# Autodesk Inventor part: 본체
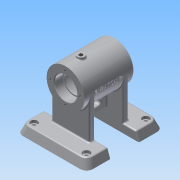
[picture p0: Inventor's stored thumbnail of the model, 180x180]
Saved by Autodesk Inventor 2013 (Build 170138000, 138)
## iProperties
Created: 2016-07
Part Number: 본체
Material: 알루미늄 6061
Document SubType Name: Modeling
Designer: Administrator
Density: 2.71 g/cm^3
Mass: 499.244 g
Surface Area: 539.605 cm^2
Volume: 184.223 cm^3
Author: Administrator
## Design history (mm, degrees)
sketch "스케치1"
  geometry: C1 r 27 at (0, 0); 1 further point
  constraints: 1 centre point, 1 coincident
  dimensions: "d0" = 54 diameter of C1
extrude "돌출1" new body sketch "스케치1" stored distance "d3" = 70; taper "d4" = 0 deg
node "작업 평면1"
sketch "스케치2"
  geometry: L1 (50, -55)-(-50, -55); L2 (-50, -55)-(-50, -20); L3 (-50, -20)-(50, -20); L4 (50, -20)-(50, -55); L5 (50, 20)-(-50, 20); L6 (-50, 20)-(-50, 55); L7 (-50, 55)-(50, 55); L8 (50, 55)-(50, 20); 1 further point
  constraints: 16 end point, 4 parallel, 2 collinear, 2 horizontal, 2 perpendicular
  dimensions: "d8" = 35 distance of L5.end L6.end; "d9" = 35 distance of L1.end L2.end; "d10" = 110 distance between parallel lines of L7 L1; "d11" = 50 distance from line of point (0, 0) L4; "d12" = 100 distance of L1.start L1.end; "d13" = 55 distance from line of point (0, 0) L1
extrude "돌출2" join sketch "스케치2" distance "d14" = 12; taper "d15" = 0 deg
sketch "스케치6"
  geometry: L1 (-48, 20.072)-(-48, -20.313); L2 (-48, -20.313)-(2, -20.313); L3 (2, -20.313)-(2, 20.072); L4 (2, 20.072)-(-48, 20.072); L5 (-27, -35)-(-27, 35) reference; 1 further point
  constraints: 8 end point, 2 parallel, 1 perpendicular, 1 vertical
  dimensions: "d28" = 21 distance between parallel lines of L1 L5; "d29" = 50 distance between parallel lines of L1 L3
extrude "돌출6" join sketch "스케치6" stored distance "d30" = 8; taper "d31" = 0 deg
sketch "스케치14"
  geometry: L1 (23, 70)-(23, 11.296); L2 (77, 70)-(77, 11.296); L3 (23, 11.296)-(77, 11.296); A1 r 27 centre (50, 70) between (77, 70) and (23, 70) reference; 1 further point
  constraints: 6 end point, 2 point on circle, 2 tangent, 1 parallel, 1 perpendicular, 1 vertical
extrude "돌출9" join sketch "스케치14" distance "d165" = 8; taper "d166" = 0 deg
sketch "스케치15"
  geometry: L1 (23, 70)-(23, 12); L2 (23, 12)-(77, 12); L3 (77, 12)-(77, 70); L4 (100, 12)-(0, 12) reference; A1 r 27 centre (50, 70) between (77, 70) and (23, 70) reference; 1 further point
  constraints: 6 end point, 2 point on circle, 2 tangent, 1 collinear, 1 parallel, 1 perpendicular, 1 vertical
extrude "돌출10" join sketch "스케치15" distance "d167" = 8; taper "d168" = 0 deg
feature "면 기울기1" dims angle "d169" = 20 deg
feature "면 기울기2" dims angle "d170" = 20 deg
feature "면 기울기3" dims angle "d171" = 20 deg
feature "면 기울기4" dims angle "d172" = 20 deg
feature "면 기울기5" dims angle "d173" = 20 deg
feature "면 기울기6" dims angle "d174" = 20 deg
fillet "모깎기17" dims "d175" = 10
fillet "모깎기18" dims "d176" = 2
fillet "모깎기19" dims "d177" = 2
fillet "모깎기20" dims "d178" = 2
fillet "모깎기21" dims "d179" = 2
fillet "모깎기22" dims "d180" = 2
fillet "모깎기23" dims "d181" = 2
fillet "모깎기24" dims "d182" = 2
fillet "모깎기25" dims "d183" = 2
fillet "모깎기26" dims "d184" = 2
sketch "스케치8"
  geometry: L1 (0, 35)-(0, -35); L2 (0, 35)-(16, 35); L3 (16, 35)-(16, 23); L4 (16, 23)-(14, 23); L5 (14, 23)-(14, 21); L6 (14, 21)-(22, 21); L7 (22, 21)-(22, -21); L8 (22, -21)-(14, -21); L9 (14, -21)-(14, -23); L10 (14, -23)-(16, -23); L11 (16, -23)-(16, -35); L12 (16, -35)-(0, -35); 2 further points
  constraints: 24 end point, 6 parallel, 5 perpendicular, 1 coincident, 1 midpoint, 1 vertical
  dimensions: "d46" = 70 distance of L1.start L1.end; "d48" = 32 diameter of L3 L1; "d49" = 28 diameter of L5 L1; "d50" = 44 diameter of L7 L1; "d51" = 28 diameter of L9 L1; "d52" = 32 diameter of L11 L1; "d53" = 12 distance of L2.end L3.end; "d54" = 42 distance of L6.end L7.end; "d55" = 12 distance of L10.end L11.end; "d56" = 2 distance of L4.end L5.end
revolve "회전1" sketch "스케치8" stored, may be unused: angle "d57" = 90 deg
fillet "모깎기9" dims "d58" = 0.3
fillet "모깎기10" dims "d59" = 3
chamfer "모따기1" distance "d60" = 1; stored, may be unused: second distance "d61" = 2, angle "d62" = 45 deg
sketch "스케치9"
  geometry: 2 further points
  constraints: 1 vertical alignment
  dimensions: "d63" = 21 distance of point (0, 0) point (0, 21)
hole "구멍1" sketch "스케치9" at (0, 21) diameter "d64" = 3.242; stored, may be unused: countersink angle "d68" = 90 deg, drill point angle "d70" = 118 deg; dims "d65" = 8, "d66" = 4, "d67" = 2, "d69" = 10
node "작업 평면2"
sketch "스케치10"
  geometry: L1 (27, 35)-(-27, 35) reference; C1 r 5 at (0, 13); 2 further points
  constraints: 1 centre point, 1 midpoint, 1 vertical alignment
  dimensions: "d76" = 22 distance from line of L1 C1.centre; "d77" = 10 diameter of C1
extrude "돌출8" join sketch "스케치10" stored distance "d78" = 8; taper "d79" = 0 deg
fillet "모깎기12" dims "d80" = 2
fillet "모깎기14" dims "d82" = 2
hole "구멍2" diameter "d85" = 5.188; stored, may be unused: countersink angle "d89" = 90 deg, drill point angle "d91" = 0 deg; dims "d83" = 10, "d84" = 10, "d86" = 19, "d87" = 4, "d88" = 2, "d90" = 20
sketch "스케치13"
  geometry: L1 (0, 0)-(-11.658, -18.657); L2 (0, 0)-(0, -35.07); L3 (-11.658, -18.657)-(-15.898, -25.441); L4 (-20.986, -22.262)-(-17.515, -16.707); L5 (-20.986, -22.262)-(-15.898, -25.441); L6 (-17.515, -16.707)-(-12.427, -19.887); 1 further point
  constraints: 12 end point, 2 perpendicular, 1 collinear, 1 point on line, 1 vertical, 2 other
  dimensions: "d113" = 32 deg angle of L1 L2; "d114" = 30 distance of L1.start L3.end; "d116" = 12 diameter of L4 L3; "d128" = 6.54998 distance between parallel lines of L5 L6
revolve "회전3" sketch "스케치13" stored, may be unused: angle "d117" = 90 deg
fillet "모깎기16" dims "d118" = 2
hole "구멍9" diameter "d187" = 5.188; stored, may be unused: countersink angle "d191" = 90 deg, drill point angle "d193" = 0 deg; dims "d185" = 10, "d186" = 10, "d188" = 19, "d189" = 10, "d190" = 4, "d192" = 20
sketch "스케치16"
  geometry: L1 (-8, -34.5)-(8, -34.5); L2 (8, -41.5)-(-8, -41.5); L3 (45.603, -70)-(22, -70) reference; A1 r 3.5 centre (8, -38) between (8, -41.5) and (8, -34.5); A2 r 3.5 centre (-8, -38) between (-8, -34.5) and (-8, -41.5); 3 further points
  constraints: 6 point on circle, 4 end point, 4 tangent, 2 centre point, 1 horizontal, 1 horizontal alignment, 1 parallel
  dimensions: "d194" = 3.5 radius of A2; "d196" = 32 distance from line of L3 point (11.5, -38); "d197" = 11.5 horizontal distance of point (0, 0) point (-11.5, -38); "d198" = 23 distance of point (11.5, -38) point (-11.5, -38)
extrude "돌출11" cut sketch "스케치16" stored distance "d199" = 8; taper "d200" = 0 deg
node "작업 평면4"
sketch "스케치17"
  geometry: L1 (27, 35)-(-27, 35) reference; L2 (27, -35)-(27, 35) reference; 2 further points
  constraints: 1 other
  dimensions: "d201" = 35 distance from line of L1 point (0, 0); "d202" = 27 distance from line of point (0, 0) L2
feature "엠보싱2" sketch "스케치17" dims "d28" = 21, "d29" = 50, "d203" = 0.5, "d204" = 0
sketch "스케치18"
  geometry: L1 (-50, -45.603)-(-50, -22) reference; L2 (40.603, -55)-(-40.603, -55) reference; 5 further points
  constraints: 2 horizontal alignment, 2 vertical alignment
  dimensions: "d205" = 85 distance of point (-37.5, -42.5) point (-37.5, 42.5); "d207" = 75 distance of point (37.5, -42.5) point (-37.5, -42.5); "d208" = 12.5 distance from line of L1 point (-37.5, -42.5); "d209" = 12.5 distance from line of L2 point (-37.5, -42.5)
hole "구멍10" sketch "스케치18" at (-37.5, -42.5), (37.5, -42.5), (37.5, 42.5), (-37.5, 42.5) diameter "d210" = 6; stored, may be unused: countersink angle "d214" = 90 deg, drill point angle "d216" = 0 deg; dims "d211" = 19, "d212" = 10, "d213" = 4, "d215" = 20
fillet "모깎기27" dims "d217" = 2
fillet "모깎기28" dims "d218" = 2
node "솔리드1"
pattern_circular "원형 패턴1" dims angle "d72" = 360 deg
mirror "대칭4"
